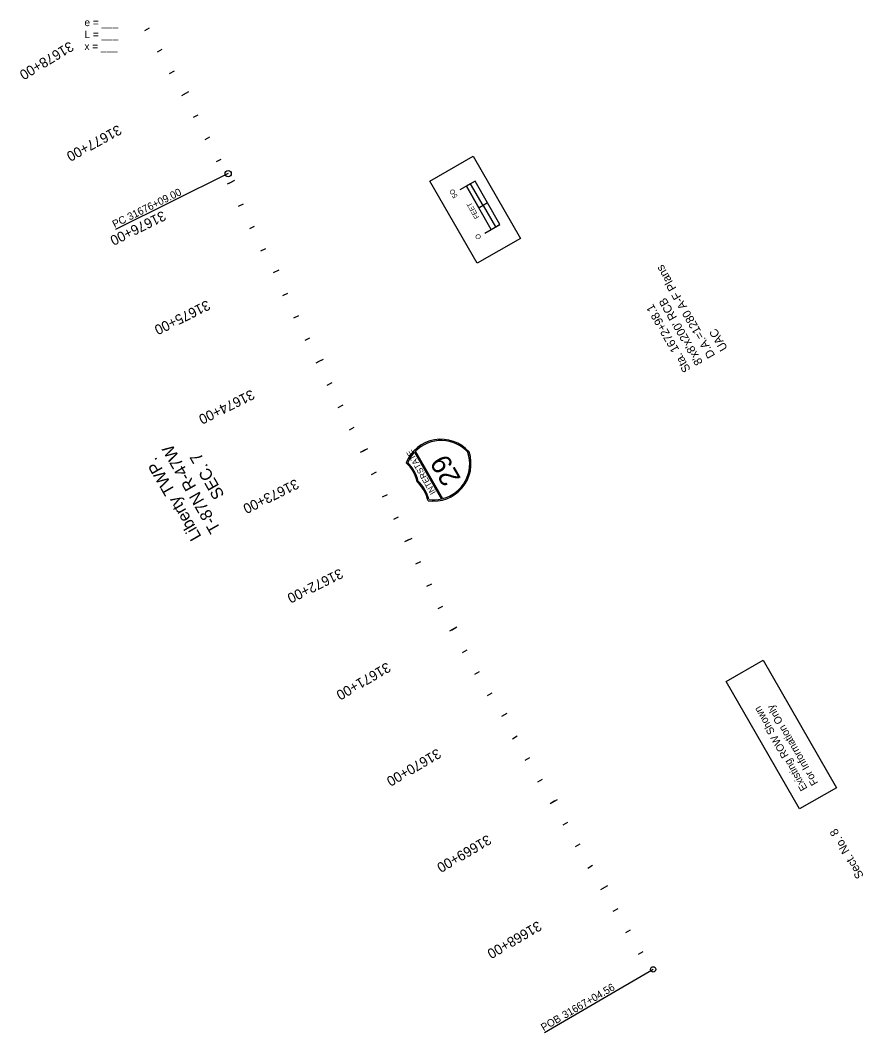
# Model space of a CAD drawing. Extents: x 14087837 to 14090046, y 8544369 to 8548535.
# Drawn here: x 14089202 to 14090046, y 8544369 to 8545383 of the extents above; entities that cross this region are included whole.
import ezdxf

# ---------------------------------------------------------------- set-up
doc = ezdxf.new("R2010")
doc.units = 0
for name, color, linetype in [('_CIVIL_CONSTRUCTION', 7, 'Continuous'), ('Default', 7, 'Continuous'), ('EXT_SNP', 7, 'Continuous'), ('Roadways', 7, 'Continuous'), ('Text', 7, 'Continuous'), ('TextAlignment', 7, 'Continuous'), ('Wetlands', 7, 'Continuous')]:
    doc.layers.add(name, color=color, linetype=linetype)

msp = doc.modelspace()

# ---------------------------------------------------------------- linework, layer by layer
at = {"layer": '_CIVIL_CONSTRUCTION'}
for p, q in [((14089409.8, 8545229.6), (14089296.9, 8545173.7)), ((14089296.9, 8545173.7), (14089296.9, 8545173.7)), ((14089835.5, 8544432.2), (14089726.6, 8544368.7)), ((14089726.6, 8544368.7), (14089726.6, 8544368.7))]:
    msp.add_line(p, q, dxfattribs=at)
for centre, radius in [((14089409.8, 8545229.6), 3.12), ((14089835.5, 8544432.2), 2.67)]:
    msp.add_circle(centre, radius, dxfattribs=at)
at = {"layer": 'EXT_SNP'}
for p, q in [((14089596.5, 8544950.5), (14089623.5, 8544903.5)), ((14089624.8, 8544903.8), (14089597.4, 8544951.5))]:
    msp.add_line(p, q, dxfattribs=at)
msp.add_lwpolyline([(14089982.2, 8544592.9), (14089908.7, 8544720.7), (14089945.7, 8544742), (14090019.2, 8544614.2)], close=True, dxfattribs=at)
for centre, radius, start, end in [((14089623, 8544925.9), 37.5, 41.4311, 158.2251), ((14089623.1, 8544925.9), 36.2, 41.8236, 135.1407), ((14089623, 8544925.9), 36.2, 137.1573, 156.8981), ((14089615.6, 8544938.9), 37.5, 261.563, 18.357), ((14089615.6, 8544938.9), 36.2, 284.6474, 17.9645), ((14089562.6, 8544912.4), 37.5, 12.903, 46.8851), ((14089562.5, 8544912.5), 38.7, 13.3195, 45.455), ((14089573.5, 8544893.4), 37.5, 12.903, 46.8851), ((14089573.5, 8544893.3), 38.7, 14.3331, 46.4686), ((14089615.6, 8544938.9), 36.2, 262.8899, 282.6306)]:
    msp.add_arc(centre, radius, start, end, dxfattribs=at)
at = {"layer": 'Roadways'}
for p, q in [((14089330.8, 8545375.5), (14089326.1, 8545372.8)), ((14089343.4, 8545353.9), (14089338.6, 8545351.2)), ((14089355.7, 8545332.2), (14089350.9, 8545329.5)), ((14089365.1, 8545308.8), (14089370.5, 8545311.8)), ((14089379.6, 8545288.3), (14089374.8, 8545285.7)), ((14089391.3, 8545266.1), (14089386.4, 8545263.6)), ((14089402.6, 8545243.9), (14089397.8, 8545241.4)), ((14089411, 8545220.1), (14089416.5, 8545222.9)), ((14089424.9, 8545199.1), (14089420, 8545196.7)), ((14089436, 8545176.7), (14089431.1, 8545174.3)), ((14089447.1, 8545154.3), (14089442.2, 8545151.9)), ((14089455.4, 8545130.5), (14089460.9, 8545133.2)), ((14089469.2, 8545109.5), (14089464.3, 8545107.1)), ((14089480.3, 8545087.1), (14089475.4, 8545084.7)), ((14089491.4, 8545064.7), (14089486.5, 8545062.3)), ((14089499.8, 8545040.9), (14089505.3, 8545043.6)), ((14089513.6, 8545019.9), (14089508.7, 8545017.4)), ((14089524.7, 8544997.5), (14089519.8, 8544995)), ((14089535.8, 8544975.1), (14089530.9, 8544972.6)), ((14089544.2, 8544951.3), (14089549.6, 8544954)), ((14089558, 8544930.3), (14089553.1, 8544927.8)), ((14089569.1, 8544907.8), (14089564.2, 8544905.4)), ((14089580.2, 8544885.4), (14089575.3, 8544883)), ((14089588.5, 8544861.7), (14089594, 8544864.4)), ((14089602.4, 8544840.6), (14089597.5, 8544838.2)), ((14089613.5, 8544818.2), (14089608.6, 8544815.8)), ((14089624.5, 8544795.8), (14089619.7, 8544793.4)), ((14089633.6, 8544772.2), (14089638.9, 8544775.3)), ((14089648.8, 8544752.1), (14089644.1, 8544749.4)), ((14089661.4, 8544730.5), (14089656.7, 8544727.8)), ((14089674, 8544708.9), (14089669.3, 8544706.2)), ((14089684, 8544685.8), (14089689.2, 8544688.9)), ((14089699.2, 8544665.8), (14089694.5, 8544663)), ((14089711.8, 8544644.2), (14089707.1, 8544641.4)), ((14089724.4, 8544622.6), (14089719.7, 8544619.8)), ((14089734.3, 8544599.4), (14089739.6, 8544602.5)), ((14089749.6, 8544579.4), (14089744.9, 8544576.6)), ((14089762.2, 8544557.8), (14089757.5, 8544555)), ((14089774.8, 8544536.2), (14089770.1, 8544533.4)), ((14089784.7, 8544513.1), (14089790, 8544516.1)), ((14089800, 8544493), (14089795.2, 8544490.3)), ((14089812.6, 8544471.4), (14089807.8, 8544468.7)), ((14089825.2, 8544449.8), (14089820.4, 8544447.1))]:
    msp.add_line(p, q, dxfattribs=at)
at = {"layer": 'Text'}
msp.add_line((14089669.5, 8545200.4), (14089660.8, 8545195.4), dxfattribs=at)
msp.add_line((14089669.5, 8545200.4), (14089660.8, 8545195.4), dxfattribs=at)
for points in [[(14089659.4, 8545139.7), (14089612, 8545222.1), (14089655.4, 8545247), (14089702.7, 8545164.7)], [(14089659.4, 8545139.7), (14089612, 8545222.1), (14089655.4, 8545247), (14089702.7, 8545164.7)], [(14089702.7, 8545164.7), (14089659.4, 8545139.7), (14089612, 8545222.1), (14089655.4, 8545247)], [(14089665.1, 8545197.8), (14089652.7, 8545219.5), (14089648.4, 8545217), (14089660.8, 8545195.4)], [(14089682, 8545178.7), (14089669.5, 8545200.4), (14089665.1, 8545197.8), (14089677.6, 8545176.2)]]:
    msp.add_lwpolyline(points, close=True, dxfattribs=at)
for points in [[(14089666.8, 8545170), (14089682, 8545178.7), (14089657.1, 8545222), (14089641.9, 8545213.3)], [(14089673.3, 8545173.7), (14089648.4, 8545217)]]:
    msp.add_lwpolyline(points, dxfattribs=at)
at = {"layer": 'Wetlands'}
for p, q in [((14089367.8, 8545310.3), (14089363, 8545307.7)), ((14089413.8, 8545221.5), (14089408.9, 8545219.1)), ((14089455.4, 8545130.5), (14089460.9, 8545133.2)), ((14089502.5, 8545042.3), (14089497.6, 8545039.8)), ((14089546.9, 8544952.7), (14089542, 8544950.2)), ((14089591.3, 8544863), (14089586.4, 8544860.6)), ((14089636.2, 8544773.7), (14089631.5, 8544771)), ((14089684, 8544685.8), (14089689.2, 8544688.9)), ((14089737, 8544601), (14089732.3, 8544598.2)), ((14089787.4, 8544514.6), (14089782.7, 8544511.8))]:
    msp.add_line(p, q, dxfattribs=at)

# ---------------------------------------------------------------- texts
at = {"layer": '_CIVIL_CONSTRUCTION'}
for s, p in [('e = ___ ', (14089265.9, 8545377.4)), ('L = ___', (14089265.9, 8545365.4)), ('x = ___', (14089265.9, 8545353.4))]:
    msp.add_text(s, height=7.5, dxfattribs=at).set_placement(p)
for s, rotation, p in [('31676+09.00', 26.3427, (14089311.1, 8545182.5)), ('PC', 26.3427, (14089296.1, 8545175.1)), ('31667+04.56', 30.2561, (14089747.1, 8544382.5)), ('POB ', 30.2561, (14089725.8, 8544370.1))]:
    msp.add_text(s, height=7.5, rotation=rotation, dxfattribs=at).set_placement(p)
at = {"layer": 'Default'}
for s, p in [('Existing ROW Shown', (14089990.3, 8544613.6)), ('For Information Only', (14090001, 8544619))]:
    msp.add_text(s, height=7.5, rotation=119.8939, dxfattribs=at).set_placement(p)
at = {"layer": 'EXT_SNP'}
for s, height, p in [('INTERSTATE', 6, (14089618.1, 8544910.1)), ('29', 20, (14089643.4, 8544924.1))]:
    msp.add_text(s, height=height, rotation=119.894, dxfattribs=at).set_placement(p)
at = {"layer": 'Roadways'}
for s, rotation, p in [('31678+00', 211.1177, (14089251.2, 8545362.5)), ('31677+00', 208.6177, (14089299.6, 8545278.8)), ('31676+00', 206.3427, (14089344.3, 8545192.7)), ('31675+00', 206.3427, (14089388.7, 8545103.1)), ('31674+00', 206.3427, (14089433.1, 8545013.5)), ('31673+00', 206.3427, (14089477.5, 8544923.9)), ('31672+00', 206.3427, (14089521.8, 8544834.2)), ('31671+00', 210.2561, (14089568.9, 8544740.3)), ('31670+00', 210.2561, (14089619.3, 8544653.9)), ('31669+00', 210.2561, (14089669.7, 8544567.5)), ('31668+00', 210.2561, (14089720.1, 8544481.1))]:
    msp.add_text(s, height=10.02, rotation=rotation, dxfattribs=at).set_placement(p)
at = {"layer": 'Text'}
for s, p in [('5O', (14089639.9, 8545206.8)), ('FEET', (14089661.6, 8545186)), ('O', (14089663.7, 8545165.3))]:
    msp.add_text(s, height=5, rotation=119.8939, dxfattribs=at).set_placement(p)
at = {"layer": 'TextAlignment'}
for s, height, p in [('D.A.=1280 A-F Plans', 8.4, (14089897.9, 8545047.4)), ('Sta. 1672+98.1', 8.4, (14089873.4, 8545033.3)), ("8'x8'x200' RCB", 8.4, (14089885.6, 8545040.4)), ('UAC', 8.4, (14089910.4, 8545054.6)), ('T-87N R-47W', 12, (14089402.7, 8544873.4)), ('SEC. 7', 12, (14089406.5, 8544907.4)), ('Liberty TWP.', 12, (14089383.4, 8544865.9)), ('Sect. No. 8', 8.4, (14090046.8, 8544525.9))]:
    msp.add_text(s, height=height, rotation=119.8939, dxfattribs=at).set_placement(p)
at = {"layer": 'Wetlands'}
for s, rotation, p in [('31675+00', 206.3427, (14089388.7, 8545103.1)), ('31670+00', 210.2561, (14089619.3, 8544653.9))]:
    msp.add_text(s, height=10.02, rotation=rotation, dxfattribs=at).set_placement(p)

doc.saveas('drawing.dxf')
